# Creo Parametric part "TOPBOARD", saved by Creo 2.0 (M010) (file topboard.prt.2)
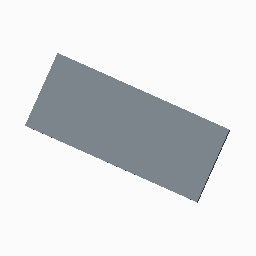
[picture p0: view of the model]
Units: Inch lbm Second (Pro/E Default); INCH, POUND, SECS

Created from: INLBS_PART_SOLID.PRT

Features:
  1. datum plane "RIGHT"
  2. datum plane "TOP"
  3. datum plane "FRONT"
  4. coordinate system
  5. sketch "Sketch 1"
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
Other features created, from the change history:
  extrusion "Extrude 1"

Surfaces: 9 plane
